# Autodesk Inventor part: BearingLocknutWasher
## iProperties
Author: mmontgomery
Created: 2001-01
Part Number: BearingLocknutWasher
Material: Steel, Mild
Document SubType Name: Modeling
Designer: mmontgomery
Control State: 0
Master: False
Checked Out: False
PropertySet Name: Design Tracking Control
Shininess: 25.0
PropertySet Name: _Private Model Information
Density: 7.86
Volumn: 0.2839292043231226
Area: 7.413985266965503
PropertySet Name: Model Information
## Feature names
1. MainBody [Revolution]
2. TangCutout [Extrusion]
3. Circular Pattern1
4. Tab [Extrusion]
5. Fillet1
6. Fillet2
